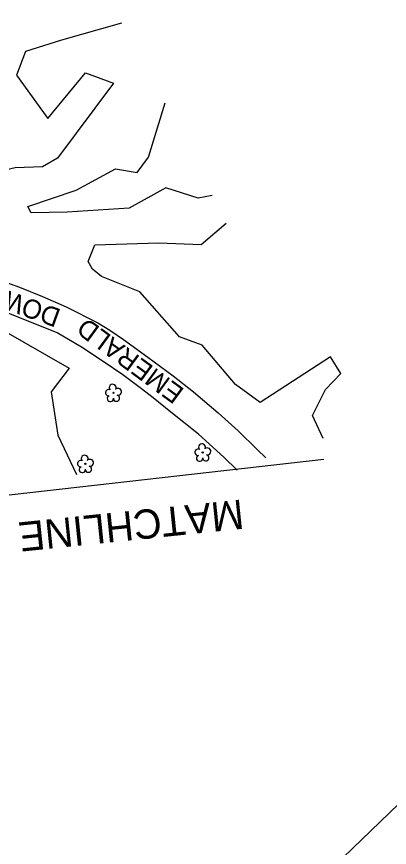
# Model space of a CAD drawing. Extents: x 474972 to 479313, y 498315 to 502691.
# Drawn here: x 477818.9 to 478022.9, y 499256.4 to 499710.1 of the extents above; entities that cross this region are included whole.
import ezdxf

# ---------------------------------------------------------------- set-up
doc = ezdxf.new("R2010")
doc.units = 0
for name, color, linetype in [('CTL Sheet Border CELL', 7, 'Continuous'), ('Exist Roads EOP', 7, 'Continuous'), ('Exist Roads EOP Text', 7, 'Continuous'), ('Exist Vegetation Tree CELL', 7, 'Continuous'), ('Exist Vegetation Woods Line', 7, 'Continuous'), ('Matchline', 7, 'Continuous'), ('Matchline Text', 7, 'Continuous')]:
    doc.layers.add(name, color=color, linetype=linetype)

msp = doc.modelspace()

# ---------------------------------------------------------------- linework, layer by layer
at = {"layer": 'CTL Sheet Border CELL'}
msp.add_lwpolyline([(475037.94, 501013.31), (477341.38, 498619.57), (479016.98, 500231.96), (476713.55, 502625.7)], close=True, dxfattribs=at)
at = {"layer": 'Exist Roads EOP'}
for points in [[(477707.88, 499589.88), (477722.16, 499587.47), (477730.89, 499585.6), (477744.44, 499582.53), (477761.14, 499578.78), (477779.27, 499574.4), (477798.64, 499569.33), (477807.56, 499566.95), (477820.5, 499562.36), (477833.18, 499557.3), (477846.07, 499551.66), (477863.4, 499542.88), (477869.88, 499538.85), (477877.39, 499533.81), (477890.81, 499524.15), (477904.64, 499513.95), (477915.66, 499505.08), (477929.16, 499493.74), (477940.15, 499483.91), (477950.57, 499473.62), (477955.31, 499469.04)], [(477939.56, 499462.4), (477932.37, 499469.51), (477918.47, 499481.95), (477903.33, 499493.99), (477893.66, 499501.94), (477887.35, 499506.88), (477877.09, 499514.45), (477866.29, 499521.77), (477854.51, 499529.64), (477841.09, 499537.31), (477827.13, 499543.08), (477811.07, 499549.49), (477795.97, 499554.98), (477775.84, 499560.75), (477759.62, 499563.89), (477745.62, 499565.92), (477730.11, 499567.18), (477723.96, 499566.83), (477720.22, 499566.9)]]:
    msp.add_lwpolyline(points, dxfattribs=at)
at = {"layer": 'Exist Vegetation Tree CELL'}
for p, q in [((477871.91, 499504.58), (477871.91, 499504.58)), ((477920.76, 499472.03), (477920.76, 499472.03)), ((477856.56, 499465.8), (477856.56, 499465.8))]:
    msp.add_line(p, q, dxfattribs=at)
for centre in [(477871.91, 499504.58), (477920.76, 499472.03), (477856.56, 499465.8)]:
    msp.add_circle(centre, 0.326, dxfattribs=at)
for centre, radius, start, end in [((477869.3, 499504.73), 1.73, 62.6636, 279.3457), ((477871.52, 499507.45), 1.86, 330.1651, 219.7134), ((477874.45, 499505.17), 1.9, 257.1011, 134.1999), ((477870.2, 499501.46), 1.69, 111.5671, 6.231), ((477873.58, 499501.68), 1.7, 181.2822, 74.56), ((477920.38, 499474.9), 1.86, 330.1651, 219.7134), ((477856.18, 499468.67), 1.86, 330.1651, 219.7134), ((477918.16, 499472.18), 1.73, 62.6636, 279.3457), ((477919.06, 499468.9), 1.69, 111.5671, 6.231), ((477922.44, 499469.13), 1.7, 181.2822, 74.56), ((477923.31, 499472.61), 1.9, 257.1011, 134.1999), ((477853.96, 499465.95), 1.73, 62.6636, 279.3457), ((477859.11, 499466.39), 1.9, 257.1011, 134.1999), ((477854.86, 499462.68), 1.69, 111.5671, 6.231), ((477858.23, 499462.9), 1.7, 181.2822, 74.56)]:
    msp.add_arc(centre, radius, start, end, dxfattribs=at)
at = {"layer": 'Exist Vegetation Woods Line'}
for points in [[(477876.38, 499706.59), (477843.58, 499697.18), (477823.77, 499691.04), (477818.96, 499678.19), (477836.09, 499654.48), (477856.54, 499679.3), (477871.93, 499673.78), (477841.32, 499632.8), (477833.17, 499627.98), (477818.22, 499627.52), (477791.9, 499621.51), (477735.64, 499607.74), (477706, 499602.05), (477689.58, 499609.97), (477652.36, 499676.12)], [(477925.96, 499612.43), (477918.26, 499610.93), (477900.52, 499616.51), (477880.49, 499605.45), (477846.64, 499603.23), (477826.98, 499602.88), (477825.12, 499606.3), (477851.46, 499615.37), (477872.95, 499627.02), (477884.83, 499625), (477891.12, 499633.24), (477900.14, 499662.95)], [(477860.47, 499572.13), (477858.03, 499576.29), (477861.73, 499585.42), (477896.79, 499586.54), (477919.84, 499585.7), (477933.66, 499597.29)], [(477986.6, 499479.61), (477980.83, 499492.25), (477987.94, 499506.47), (477996.27, 499515.12), (477990.62, 499524.29), (477952.23, 499499.42), (477938.68, 499509.24), (477920.41, 499530.64), (477907.98, 499535.21), (477886.31, 499559.78), (477865.46, 499568.07), (477860.47, 499572.13)], [(477775.6, 499445.19), (477773.29, 499450.05), (477744.13, 499520.27), (477757.06, 499536.14), (477773.74, 499534.94), (477797.95, 499546.46), (477847.63, 499518.13), (477837.84, 499505.13), (477841.46, 499481.55), (477851.69, 499460.06)]]:
    msp.add_lwpolyline(points, dxfattribs=at)
at = {"layer": 'Matchline'}
msp.add_line((477986.93, 499468.27), (477490.12, 499411.83), dxfattribs=at)

# ---------------------------------------------------------------- texts
at = {"layer": 'Exist Roads EOP Text'}
for s, rotation, p in [('DOWNS DR', 160.0879, (477843.76, 499549.97)), ('EMERALD', 143.7143, (477911.2, 499506.36))]:
    msp.add_text(s, height=10.4, rotation=rotation, dxfattribs=at).set_placement(p)
at = {"layer": 'Matchline Text'}
msp.add_text('MATCHLINE SHEET RW02C-4', height=16, rotation=185.8839, dxfattribs=at).set_placement((477942.29, 499446.41))

doc.saveas('drawing.dxf')
